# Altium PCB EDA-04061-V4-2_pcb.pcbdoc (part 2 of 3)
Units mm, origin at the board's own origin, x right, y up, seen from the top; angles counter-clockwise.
Board outline 105 x 56 mm, 6 copper layers (Top Layer, L2, L3, L4, L5, Bottom Layer), stack 1.58 mm thick; 213 components, 137 nets, 766 pads, 477 vias.
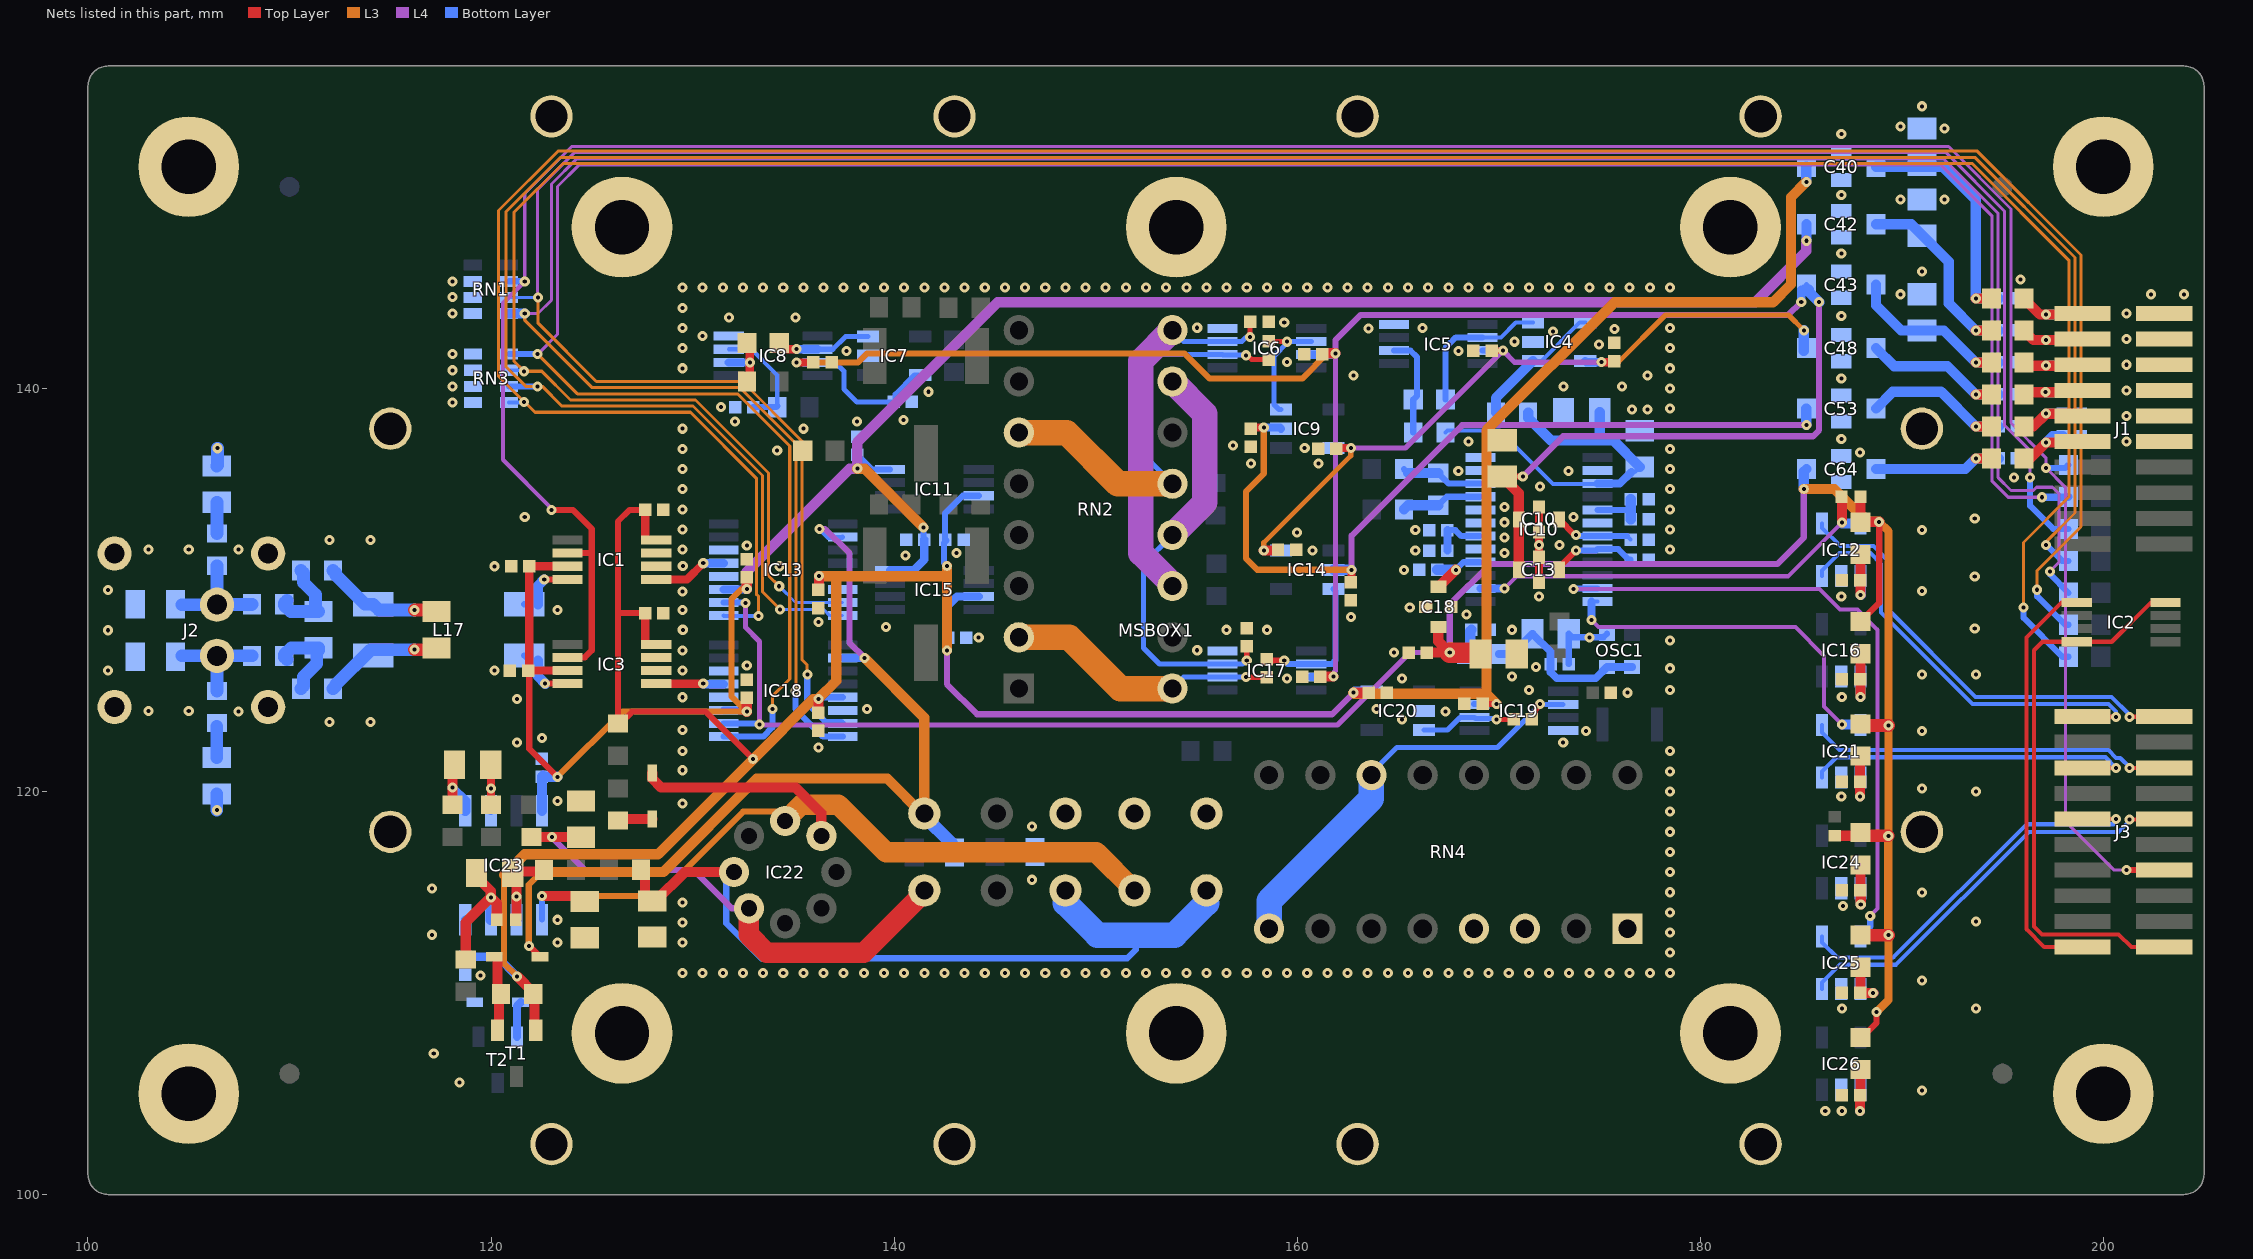
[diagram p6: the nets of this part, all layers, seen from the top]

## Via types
v1: diameter 0.5, hole 0.2, Top Layer to Bottom Layer, tented both sides, 477 vias

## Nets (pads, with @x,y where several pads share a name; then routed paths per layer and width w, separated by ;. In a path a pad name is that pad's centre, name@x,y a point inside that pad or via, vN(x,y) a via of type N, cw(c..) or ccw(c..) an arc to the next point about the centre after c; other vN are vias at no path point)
2V5_DIGITAL: C18.3 C21.2 C22.1 C64.1 C78.1 IC13.2 IC18.2 L7.1 L8.1 L9.1 L10.1 L11.2 L12.2 L20.1 R4.2 R18.2 | length 120
  Top Layer w0.305: L12.2@187.96,107.798 188.031,107.798 188.754,108.52 v1(188.754,109.061) ; L8.1@187.96,128.435 188.882,129.357 v1(188.882,133.381)
  Top Layer w0.508: C22.1@166.432,126.892 v1(167.572,126.892) 167.005,127.46 C18.3@167.005,128.159 ; C21.2@168.75,126.892 169.03,126.892 C21.2@169.1,126.822 ; R18.2@186.665,117.8 187.802,117.8 L10.1@187.96,117.958 ; R4.2@187.954,134.62 187.96,134.614 L7.1@187.96,133.356 187.985,133.381 v1(188.882,133.381)
  Top Layer w0.635: L11.2@187.96,112.878 187.968,112.869 v1(189.34,112.869) ; L10.1@187.96,117.958 188.118,117.8 v1(189.332,117.8) ; L9.1@187.96,123.355 188.038,123.277 v1(189.348,123.277)
  Top Layer w1.016: v1(167.572,126.892) C21.2@168.75,126.892
  L4 w0.254: v1(132.627,129.357) 132.627,128.147 133.325,127.449 v1(133.325,123.325) 133.35,123.3 162.002,123.3 165.594,126.892 v1(167.572,126.892)
  L4 w0.305: v1(167.572,126.892) 167.572,129.28 169.573,131.281 183.826,131.281 185.141,132.596 v1(185.141,135.009)
  L3 w0.406: v1(188.754,109.061) 189.34,109.647 v1(189.34,112.869) 189.332,112.877 v1(189.332,117.8) 189.348,117.816 v1(189.348,123.277) 189.348,132.915 v1(188.882,133.381)
  L3 w0.508: v1(185.141,135.009) 186.66,135.009 188.288,133.381 v1(188.882,133.381)
  Bottom Layer w0.305: IC13.2@131.547,129.376 132.608,129.376 v1(132.627,129.357) ; IC18.2@131.55,123.375 133.275,123.375 v1(133.325,123.325)
  Bottom Layer w0.508: L20.1@168.4,126.822 168.594,127.016 168.594,127.968 C78.1@168.65,128.024 ; v1(185.141,135.009) 185.141,135.866 C64.1@185.275,136
  Bottom Layer w0.635: v1(167.572,126.892) 168.33,126.892 L20.1@168.4,126.822
7V1: D2.1 IC13.10 IC18.10 R9.2 R12.2 R13.2 R38.2 RN4.1 RN4.3 RN4.4 | length 47.9
  Top Layer w0.305: v1(121.873,112.325) 121.912,112.325 D2.1@122.438,111.799
  L4 w0.305: v1(136.297,133.033) 136.571,133.033 137.795,131.809 137.795,127.364 v1(138.532,126.627)
  L3 w0.305: v1(121.873,112.325) 121.873,115.369 122.504,116
  L3 w0.508: 122.504,116 128.54,116 133.182,120.642 139.656,120.642 141.5,118.798 141.5,123.659 v1(138.532,126.627)
  Bottom Layer w0.254: v1(136.297,133.033) 136.734,132.596 137.417,132.596 IC13.10@137.447,132.626
  Bottom Layer w0.406: IC18.10@137.45,126.625 138.53,126.625 v1(138.532,126.627)
  Bottom Layer w0.635: R9.2@141.5,118.904 141.5,118.774 142.843,117.431 142.843,117.133 R38.2@143,116.975
+5V: C4.2 C5.1 C7.2 C10.1 C13.1 C24.2 C43.1 C56.2 IC6.7 IC7.5 IC8.7 IC17.7 | length 111.6
  Top Layer w0.305: C7.2@170.18,135.625 v1(171.196,135.625)
  Top Layer w0.406: v1(135.165,141.294) C5.1@136,141.294
  Top Layer w0.508: C24.2@161.15,125.7 v1(161.8,125.7) ; C4.2@161.25,141.7 161.29,141.74 v1(161.9,141.74) ; C7.2@170.18,135.625 171,134.805 C10.1@171,133.5 C13.1@171,131
  L4 w0.254: v1(161.8,125.7) 161.847,125.747 161.847,125.939 161.9,125.992 v1(161.9,141.74)
  L4 w0.305: v1(161.9,141.74) 161.9,142.4 163.145,143.645 184.379,143.645 v1(185.014,144.28) ; v1(171.196,135.625) 173.196,137.625 185.598,137.625 185.903,137.93 v1(185.903,144.28)
  L3 w0.305: v1(135.165,141.294) 138.213,141.294 138.659,141.74 154.404,141.74 155.652,140.492 160.252,140.492 161.5,141.74 v1(161.9,141.74)
  Bottom Layer w0.254: v1(135.165,141.294) 137.073,141.294 137.516,140.851 137.516,139.962 138.151,139.327 C56.2@139.987,139.327 140.056,139.327 140.056,139.708 141.017,140.669 IC7.5@141.3,140.669 ; v1@161.775,125.675 v1(161.8,125.7) ; v1@161.835,141.675 v1(161.9,141.74) ; C43.1@185.014,144.915 185.134,145.035 185.275,145.035 C43.1@185.275,145.15 185.453,144.973 C43.1@185.395,144.915
  Bottom Layer w0.406: IC17.7@160.7,125.675 v1@161.775,125.675 ; IC6.7@160.7,141.675 v1@161.835,141.675 ; v1(185.014,144.28) C43.1@185.014,144.915
  Bottom Layer w0.508: C43.1@185.395,144.915 185.395,144.788 v1(185.903,144.28)
+7.5V: C2.1 C3.2 C9.2 C12.1 C48.1 IC4.5 IC5.7 IC9.5 IC14.5 | length 40.3
  Top Layer w0.305: C3.2@169.65,141.879 v1(170.212,141.879)
  Top Layer w0.406: C9.2@161.95,137 161.991,137.041 v1(162.662,137.041) ; v1(175.108,141.301) 175.685,141.301 C2.1@175.743,141.359
  Top Layer w0.508: v1(158.344,131.961) 159.011,131.961 C12.1@159.05,132
  L4 w0.254: v1(162.662,137.041) 165.374,137.041 v1(170.212,141.879) 170.79,141.301 v1(175.108,141.301)
  L3 w0.254: v1(158.344,131.961) 158.344,132.342 162.662,136.66 v1(162.662,137.041) ; v1(175.108,141.301) 175.939,141.301 178.283,143.645 184.379,143.645 v1(185.141,142.883)
  Bottom Layer w0.203: C48.1@185.142,141.867 C48.1@185.275,142
  Bottom Layer w0.305: v1(158.344,131.961) 158.355,131.95 IC14.5@159.2,131.95 ; IC9.5@161.8,137.05 162.653,137.05 v1(162.662,137.041) ; IC5.7@169.2,141.879 v1(170.212,141.879)
  Bottom Layer w0.406: IC4.5@174.3,141.363 174.362,141.301 v1(175.108,141.301)
  Bottom Layer w0.508: C48.1@185.141,141.867 v1(185.141,142.883)
+15V: C11.2 C19.1 C20.2 C27.1 C28.2 C29.1 C40.1 C72.1 C79.2 C83.2 IC1.4 IC3.4 IC11.7 IC13.13 IC15.7 IC18.13 IC19.7 IC20.5 IC23.8 R8.2 R23.2 T1.1 | length 158.2
  Top Layer w0.305: IC3.4@127.65,127.3 IC3.4@128.2,127.3 ; C20.2@127.65,128.85 126.3,128.85 ; C11.2@127.65,133.975 126.876,133.975 126.3,133.399 126.3,128.85 ; v1(133.004,121.607) 130.65,123.96 127,123.96 126.415,123.375 R8.2@126.3,123.375 126.3,128.85 ; C28.2@169.2,124.341 v1(169.901,124.341)
  Top Layer w0.406: IC3.4@127.65,127.3 C20.2@127.65,128.85 ; C11.2@127.65,133.975 127.651,132.475 IC1.4@128.2,132.475
  Top Layer w0.508: v1(121.298,110.823) 122.098,110.023 R23.2@122.098,109.956 122.16,109.894 122.16,108.212 T1.1@122.221,108.15 ; C29.1@136.246,123.902 v1(136.246,124.595) ; C19.1@136.246,129.998 136.271,130.023 v1(136.271,130.683) ; v1(162.8,124.9) C27.1@163.55,124.9
  L4 w0.305: v1(142.621,127) 142.621,125.332 144.12,123.833 161.733,123.833 v1(162.8,124.9)
  L3 w0.305: 120.64,115.858 120.64,111.481 v1(121.298,110.823)
  L3 w0.508: 120.64,115.858 121.673,116.891 128.288,116.891 v1(133.004,121.607) 135.992,124.595 v1(136.246,124.595) 137.135,125.484 137.135,130.683 ; v1(136.271,130.683) 137.135,130.683 ; v1(142.621,127) 142.621,130.683 ; v1(142.621,131.191) 142.621,130.683 ; v1(162.8,124.9) 162.851,124.849 169.393,124.849 ; v1(169.901,124.341) 169.393,124.849 ; v1(185.268,150.249) 184.506,149.487 184.506,145.169 183.617,144.28 175.755,144.28 169.393,137.918 169.393,124.849 ; 137.135,130.683 142.621,130.683
  Bottom Layer w0.254: v1(142.621,127) v1@142.679,127.058 ; v1(162.8,124.9) v1@162.85,124.95 ; IC19.7@168.784,124.341 IC19.7@168.8,124.325
  Bottom Layer w0.305: v1(136.246,124.595) 136.326,124.675 IC18.13@137.45,124.675 ; C72.1@142.55,132.5 142.596,132.454 C72.1@142.53,132.388 ; v1(142.621,131.191) 142.469,131.343 142.469,132.327 C72.1@142.53,132.388 ; IC11.7@144.2,134.675 143.405,134.675 142.53,133.8 C72.1@142.53,132.388 ; IC19.7@168.784,124.341 v1(169.901,124.341)
  Bottom Layer w0.406: IC23.8@118.72,113.64 C83.2@118.72,111.799 120.322,111.799 v1(121.298,110.823) ; v1(136.271,130.683) 136.278,130.676 IC13.13@137.447,130.676 ; v1@142.679,127.058 C79.2@142.679,127.635 142.679,129.227 143.127,129.675 IC15.7@144.2,129.675
  Bottom Layer w0.508: v1@162.85,124.95 IC20.5@163.7,124.95 ; v1(185.268,150.249) 185.268,151.011 185.275,151.004 C40.1@185.275,151
-2.5V: C6.1 C17.1 C53.1 IC9.2 IC14.2 | length 42.8
  Top Layer w0.406: C6.1@157.709,137.999 157.767,138.057 v1(158.344,138.057) ; C17.1@162.662,130.379 162.7,130.417 v1(162.7,131)
  L4 w0.305: v1(162.7,131) 162.7,132.7 168.184,138.184 v1(185.268,138.184)
  L3 w0.305: v1(158.344,138.057) 158.344,135.771 157.455,134.882 157.455,131.568 158.023,131 v1(162.7,131)
  Bottom Layer w0.406: v1(158.344,138.057) 159.143,138.057 IC9.2@159.2,138
  Bottom Layer w0.508: IC14.2@161.8,131 v1(162.7,131) ; v1(185.268,138.184) 185.268,138.993 C53.1@185.275,139
-15V: C14.1 C15.2 C23.2 C26.1 C42.1 C63.1 C73.2 C82.2 IC1.7 IC3.7 IC11.4 IC13.3 IC15.4 IC18.3 IC23.4 | length 111.4
  Top Layer w0.305: C23.2@121.835,126 121.895,125.94 121.895,122.122 v1(123.292,120.725)
  Top Layer w0.406: IC3.7@123.8,126 C23.2@121.835,126 121.895,126.06 C15.2@121.895,131.175 IC1.7@123.8,131.175
  Top Layer w0.508: v1(132.69,123.96) C26.1@132.69,124.653 ; v1(132.69,130.056) C14.1@132.69,130.622
  L4 w0.508: v1(132.69,130.056) 132.69,130.912 137.795,136.017 v1(138.176,136.017) 138.176,137.32 145.136,144.28 182.728,144.28 185.268,146.82 v1(185.268,147.328)
  L3 w0.305: v1(123.292,120.725) 126.527,123.96 v1(132.69,123.96) 131.928,124.722 131.928,129.548 132.436,130.056 v1(132.69,130.056)
  L3 w0.508: v1(138.176,136.017) 138.54,136.017 v1(141.453,133.104)
  Bottom Layer w0.305: v1@132.625,124.025 v1(132.69,123.96) ; C63.1@138.176,136.71 138.911,135.975 IC11.4@139.8,135.975 ; v1(141.453,133.104) 141.453,132.547 C73.2@141.5,132.5 ; v1(185.268,147.328) v1@185.275,147.335
  Bottom Layer w0.406: IC13.3@131.547,130.026 132.66,130.026 v1(132.69,130.056) ; IC18.3@131.55,124.025 v1@132.625,124.025 ; v1(138.176,136.017) C63.1@138.176,136.71 ; IC15.4@139.8,130.975 140.961,130.975 141.5,131.514 C73.2@141.5,132.5
  Bottom Layer w0.508: IC23.4@122.53,119.04 122.527,119.043 122.527,120.722 C82.2@122.523,120.725 122.579,120.781 122.635,120.725 v1(123.292,120.725) ; v1@185.275,147.335 C42.1@185.275,148.15
A0_N: IC13.1 L19.2 RN3.8 | length 134.4
  L3 w0.152: v1(133.282,128.707) 133.282,129.672 133.166,129.787 133.166,135.549 129.896,138.819 122.181,138.819 121.673,139.327 v1(121.641,139.327) 120.371,140.597 120.371,148.825 123.319,151.773 193.75,151.773 198.9,146.623 198.9,133.139 196.716,130.955 v1(196.716,130.01)
  Bottom Layer w0.203: RN3.8@120.9,139.3 121.614,139.3 v1(121.641,139.327) ; IC13.1@131.547,128.726 131.566,128.707 v1(133.282,128.707)
  Bottom Layer w0.305: v1(196.716,130.01) 196.716,129.676 198.122,128.27 L19.2@198.272,128.27
A0_P: IC18.1 L14.2 RN3.5 | length 131.4
  L4 w0.152: v1(122.316,141.7) 123.302,142.687 123.302,150.019 124.376,151.093 191.944,151.093 194.469,148.568 194.469,135.414 195.282,134.6 v1(196.954,134.6)
  L3 w0.152: v1(122.316,141.7) 124.282,139.733 132.231,139.733 134.824,137.14 134.824,125.586 133.96,124.722 v1(133.96,124.087)
  Bottom Layer w0.305: RN3.5@120.9,141.7 v1(122.316,141.7) ; IC18.1@131.55,122.725 133.506,122.725 133.96,123.179 v1(133.96,124.087)
  Bottom Layer w0.381: v1(196.954,134.6) 198.253,134.6 L14.2@198.272,134.62
A1_N: IC13.16 L16.2 RN3.7 | length 131.6
  L3 w0.152: v1(134.341,129.04) 133.469,129.912 133.469,135.677 130.022,139.124 123.51,139.124 122.534,140.1 v1(122.316,140.1) 121.719,140.1 120.752,141.067 120.752,148.775 123.445,151.468 193.624,151.468 198.598,146.495 198.598,133.818 197.167,132.388 v1(197.167,132.239)
  Bottom Layer w0.152: v1(134.341,129.04) 136.5,129.04 136.814,128.726 IC13.16@137.447,128.726
  Bottom Layer w0.305: RN3.7@120.9,140.1 v1(122.316,140.1) ; v1(197.167,132.239) 197.961,131.445 L16.2@198.272,131.445
A1_P: IC18.16 L18.2 RN1.8 | length 136.1
  L4 w0.152: v1(121.673,143.715) 122.334,143.715 123,144.381 123,150.145 124.251,151.395 192.073,151.395 194.786,148.682 194.786,135.572 195.421,134.938 196.532,134.938 196.691,135.096 197.485,135.096 197.802,134.779 197.802,131.369 v1(197.358,130.924)
  L3 w0.152: v1(121.673,143.715) 121.673,143.387 125.022,140.038 132.353,140.038 135.126,137.266 135.126,124.999 v1(135.103,124.976)
  Bottom Layer w0.305: v1(135.103,124.976) 135.103,124.087 136.465,122.725 IC18.16@137.45,122.725 ; v1(197.358,130.924) 197.358,130.772 L18.2@198.272,129.857
  Bottom Layer w0.508: RN1.8@120.89,143.715 v1(121.673,143.715)
A2_N: IC13.15 L21.2 RN3.6 | length 134.3
  L3 w0.152: v1(134.3,130.183) 133.771,130.712 133.771,135.806 130.149,139.429 123.942,139.429 122.519,140.851 v1(121.641,140.851) 121.133,141.359 121.133,148.725 123.571,151.163 193.498,151.163 198.295,146.366 198.295,134.609 196.044,132.358 v1(196.044,129.127)
  Bottom Layer w0.152: RN3.6@120.9,140.9 121.592,140.9 v1(121.641,140.851) ; v1(134.3,130.183) 135.107,129.376 IC13.15@137.447,129.376
  Bottom Layer w0.305: v1(196.044,129.127) 196.044,128.609 197.97,126.682 L21.2@198.272,126.682
A2_P: IC18.15 L15.2 RN1.7 | length 131.2
  L4 w0.152: v1(122.32,144.501) 122.316,144.506 122.316,149.888 124.125,151.698 192.201,151.698 195.104,148.795 195.104,138.172 196.374,136.902 v1(196.374,135.572)
  L3 w0.152: v1(122.32,144.501) 122.32,143.251 125.228,140.343 132.476,140.343 135.433,137.386 135.433,126.535 135.682,126.287 135.682,125.822 v1(135.696,125.808)
  Bottom Layer w0.152: RN1.7@120.89,144.515 120.904,144.501 v1(122.32,144.501)
  Bottom Layer w0.305: v1(135.696,125.808) 135.694,125.806 135.694,124.366 136.612,123.448 137.377,123.448 IC18.15@137.45,123.375 ; v1(196.374,135.572) 196.374,134.167 197.508,133.032 L15.2@198.272,133.032
AIN+: C66.2 IC10.21 R30.2 | length 4.1
  Bottom Layer w0.305: C66.2@167,134.2 167.425,134.625 IC10.21@169.1,134.625
  Bottom Layer w0.508: R30.2@165.3,134 165.5,134.2 C66.2@167,134.2
AIN-: C66.1 IC10.22 R28.2 | length 4.1
  Bottom Layer w0.305: R28.2@165.3,136 R28.2@165.5,135.8 ; C66.1@167,135.8 167.525,135.275 IC10.22@169.1,135.275
  Bottom Layer w0.508: R28.2@165.5,135.8 C66.1@167,135.8
CS: IC10.14 IC12.5 R4.1 | length 21.5
  Top Layer w0.508: R4.1@187.014,134.62 187.034,134.6 v1(187.034,133.355)
  L4 w0.203: v1(170.282,130.075) 170.885,130.678 184.357,130.678 v1(187.034,133.355)
  Bottom Layer w0.406: IC10.14@169.1,130.075 v1(170.282,130.075)
  Bottom Layer w0.508: v1(187.034,133.355) 187.034,133.3 IC12.5@187.95,133.3
CS_DIFF_N: IC12.4 J3.2 | length 22.6
  Top Layer w0.203: v1(201.295,123.706) 203.02,123.706 J3.2@203.029,123.715
  Bottom Layer w0.203: IC12.4@186.05,133.3 186.05,133.084 186.956,132.178 188.59,132.178 189.332,131.436 189.332,129.033 193.669,124.697 200.406,124.697 201.295,123.808 v1(201.295,123.706)
CS_DIFF_P: IC12.3 J3.1 | length 21.8
  Top Layer w0.203: J3.1@198.965,123.715 198.974,123.706 v1(200.635,123.706)
  Bottom Layer w0.203: IC12.3@186.05,130.7 186.05,130.959 186.913,131.822 188.443,131.822 188.976,131.289 188.976,128.886 193.522,124.341 200.254,124.341 200.635,123.96 v1(200.635,123.706)
DIN: IC10.12 IC21.5 | length 18.2
  L4 w0.203: v1(174.604,128.502) 174.947,128.159 184.725,128.159 186.152,126.732 186.152,124.208 v1(187.035,123.325)
  Bottom Layer w0.203: IC10.12@174.604,129.417 174.6,129.421 174.604,129.425 IC10.12@174.9,129.425
  Bottom Layer w0.406: v1(174.604,128.502) IC10.12@174.604,129.417
  Bottom Layer w0.508: v1(187.035,123.325) 187.925,123.325 IC21.5@187.95,123.3
DIN_DIFF_N: IC21.4 J3.6 | length 18.2
  Top Layer w0.203: v1(201.295,121.158) 203.012,121.158 J3.6@203.029,121.175
  Bottom Layer w0.203: IC21.4@186.05,123.3 186.05,122.924 186.919,122.055 200.249,122.055 200.636,121.668 200.843,121.668 201.324,121.187 v1(201.295,121.158)
DIN_DIFF_P: IC21.3 J3.5 | length 17.1
  Top Layer w0.203: J3.5@198.965,121.175 198.974,121.166 v1(200.635,121.166)
  Bottom Layer w0.203: IC21.3@186.05,120.7 186.05,120.982 186.768,121.699 200.102,121.699 v1(200.635,121.166)
DOUT: IC10.11 IC25.5 | length 32.8
  L4 w0.203: v1(173.711,130.056) 185.91,130.056 186.934,129.032 187.796,129.032 188.805,128.023 188.805,114.193 v1(188.436,113.824)
  Bottom Layer w0.305: v1(173.711,130.056) 173.73,130.075 IC10.11@174.9,130.075 ; IC25.5@187.95,112.8 187.941,112.81 187.935,112.815 IC25.5@187.946,112.815 ; v1(188.436,113.824) 188.436,113.305 IC25.5@187.946,112.815 ; IC25.5@187.946,112.815 187.966,112.815 187.935,112.784 187.925,112.794 IC25.5@187.946,112.815
DOUT_DIFF_N: IC25.3 J3.10 | length 20.7
  Top Layer w0.203: v1(201.295,118.618) 203.012,118.618 J3.10@203.029,118.635
  Bottom Layer w0.203: IC25.3@186.05,110.2 186.05,110.518 186.936,111.404 189.725,111.404 196.312,117.991 200.762,117.991 201.295,118.524 v1(201.295,118.618)
DOUT_DIFF_P: IC25.4 J3.9 | length 19.8
  Top Layer w0.203: J3.9@198.965,118.635 200.626,118.635 v1(200.635,118.626)
  Bottom Layer w0.203: IC25.4@186.05,112.8 186.05,112.51 186.8,111.76 189.578,111.76 196.19,118.372 200.508,118.372 200.635,118.499 v1(200.635,118.626)
GND: B1.1 B2.1 B3.1 B4.1 B5.1 B6.1 B7.1 B8.1 B9.1 B10.1 C2.2 C3.1 C4.1 C5.2 C6.2 C7.1 C8.1 C9.1 C10.2 C11.1 C12.2 C13.2 C14.2 C15.1 C16.2 C17.2 C18.2 C19.2 C20.1 C21.1 C22.2 C23.1 C24.1 C25.2 C26.2 C27.2 C28.1 C29.2 C31.2 C32.1 C34.2 C35.1 C36.1 C37.2 C38.2 C39.2 C40.2 C41.2 C42.2 C43.2 C44.2 C45.2 C46.1 C47.2 C48.2 C49.1 C50.2 C51.1 C52.1 C53.2 C55.2 C56.1 C57.1 C58.1 C59.1 C60.1 C61.2 C62.1 C63.2 C64.2 C65.2 C67.1 C68.1 C69.2 C70.1 C71.1 C72.2 C73.1 C74.2 C75.1 C76.1 C77.1 C78.2 C79.1 C80.2 C81.1 C82.1 C83.1 C85.1 C89.1 C91.1 D3.1 IC1.2 IC1.3 IC3.2 IC3.3 IC4.2 IC5.4 IC6.4 IC7.2 IC8.4 IC10.2 IC10.6 IC10.17 IC10.19 IC10.20 IC10.23 IC10.24 IC12.2 IC13.4 IC13.6 IC13.14 IC16.2 IC17.4 IC18.4 IC18.6 IC18.14 IC19.4 IC20.2 IC21.2 IC24.2 IC25.2 IC26.2 J1.2 J1.4 J1.6 J1.8 J1.10 J1.12 J2.3 MSBOX1.1 MSBOX1.2 MSBOX1.3 MSBOX1.4 MSBOX1.5 MSBOX1.6 MSBOX1.7 MSBOX1.8 MSBOX1.9 MSBOX1.10 MSBOX1.11 MSBOX1.12 OSC1.2 R11.1 R31.1 R34.1 R37.1 RN1.1 RN1.2 RN1.3 RN3.1 RN3.2 RN3.3 RN3.4 | length 9
  Top Layer w0.406: C13.2@172,130.375 C13.2@172,131.625 C10.2@172,132.875 C10.2@172,134.125
  Bottom Layer w0.305: C80.2@173.475,126.325 C77.1@173.475,127.825 173.65,127.65 v1(174.5,127.65) 175.2,127.65 OSC1.2@175.375,127.825
  Bottom Layer w0.635: v1(106.394,119.07) C81.1@106.394,119.881 ; C70.1@106.394,136.155 106.425,136.186 v1(106.425,137.033)
  other v1: 186.205,104.148 187.025,104.148 191,105.164 118.427,105.569 117.157,106.998 187.035,109.228 193.675,109.228 191,110.62 119.471,110.861 129.5,111 130.5,111 131.5,111 132.5,111 133.5,111 134.5,111 135.5,111 136.5,111 137.5,111 138.5,111 139.5,111 140.5,111 141.5,111 142.5,111 143.5,111 144.5,111 145.5,111 146.5,111 147.5,111 148.5,111 149.5,111 150.5,111 151.5,111 152.5,111 153.5,111 154.5,111 155.5,111 156.5,111 157.5,111 158.5,111 159.5,111 160.5,111 161.5,111 162.5,111 163.5,111 164.5,111 165.5,111 166.5,111 167.5,111 168.5,111 169.5,111 170.5,111 171.5,111 172.5,111 173.5,111 174.5,111 175.5,111 176.5,111 177.5,111 178.5,111 178.5,112 123.292,112.5 129.5,112.5 117.069,112.889 178.5,113 129.5,113.5 193.675,113.538 123.292,113.634 178.5,114 187.076,114.308 129.5,114.5 191,114.984 178.5,115 117.069,115.192 146.844,115.619 178.5,116 178.5,117 178.5,118 146.844,118.269 178.5,119 129.5,119.41 123.292,119.526 187,119.757 178.5,120 193.675,119.998 191,120.15 178.5,121 129.5,121.053 129.5,122 178.5,122 136.246,122.182 121.298,122.436 173.203,122.436 122.53,122.65 174.331,122.998 191,122.998 129.5,123.05 111.989,123.452 114.021,123.452 165.202,123.579 107.474,123.96 167.361,123.96 103,124 105,124 138.659,124.087 163.932,124.087 121.298,124.595 129.5,124.675 187.025,124.697 176.39,124.9 171.5,125.025 178.5,125.025 159.487,125.611 165.202,125.611 170.663,125.7 191,125.802 193.675,125.802 101,126 120.177,126 129.5,126 178.5,126.114 171.848,126.175 132.69,126.246 164.8,126.892 129.5,127 155.042,127.008 178.5,127.5 144.2,127.635 101,128 129.515,128.024 156.5,128.024 158.494,128.024 170.663,128.024 193.624,128.08 139.605,128.159 136.246,128.405 162.662,128.659 168.4,128.788 123.292,129 129.5,129 165.588,129.139 172.009,129.675 187,129.675 129.5,129.921 191,129.945 101,130 193.624,130.675 165.3,131 120.177,131.175 134.317,131.175 129.515,131.191 140.564,131.707 143.104,131.834 170.282,131.834 160.757,131.961 165.862,131.953 103,132 105,132 107.474,132 129.5,132 178.5,132 132.69,132.215 172.009,132.24 173.025,132.24 111.989,132.469 114.021,132.469 170.282,132.596 159.995,132.85 165.862,132.969 191,132.969 129.5,133 178.5,133 170.282,133.358 193.624,133.555 121.673,133.612 173.711,133.612 129.5,134 178.5,134 170.282,134.12 129.5,135 178.5,135 172.06,135.136 195.58,135.572 167.996,135.898 173.457,135.898 129.5,136 178.5,136 157.709,136.279 161.05,136.279 187.925,136.816 134.201,136.912 129.5,137 178.5,137 160.376,137.041 156.82,137.168 168.5,137.365 201.143,137.365 187,137.5 129.5,138 135.5,138 132.113,138.35 138.151,138.35 140.462,138.43 201.143,138.635 176.625,138.946 177.394,138.946 178.5,139 131.42,139.073 118.087,139.3 141.705,139.835 201.143,139.905 178.5,140 118.087,140.1 173.215,140.1 176.124,140.1 187,140.5 162.8,140.644 177.394,140.644 118.087,140.9 129.5,141 178.5,141 201.143,141.175 159.487,141.301 118.087,141.7 137.643,141.867 168,141.867 129.5,142 178.5,142 174.981,142.19 170.79,142.317 201.143,142.445 130.5,142.594 172.695,142.825 175.743,142.952 163.55,142.975 129.5,143 155.042,143.01 166.23,143 178.5,143 159.36,143.266 131.8,143.518 135.103,143.518 187,143.6 118.087,143.715 201.143,143.715 129.5,144 118.087,144.534 189.942,144.672 202.372,144.672 204,144.672 129.5,145 130.5,145 131.5,145 132.5,145 133.5,145 134.5,145 135.5,145 136.5,145 137.5,145 138.5,145 139.5,145 140.5,145 141.5,145 142.5,145 143.5,145 144.5,145 145.5,145 146.5,145 147.5,145 148.5,145 149.5,145 150.5,145 151.5,145 152.5,145 153.5,145 154.5,145 155.5,145 156.5,145 157.5,145 158.5,145 159.5,145 160.5,145 161.5,145 162.5,145 163.5,145 164.5,145 165.5,145 166.5,145 167.5,145 168.5,145 169.5,145 170.5,145 171.5,145 172.5,145 173.5,145 174.5,145 175.5,145 176.5,145 177.5,145 178.5,145 118.087,145.315 195.897,145.415 191,145.8 187,146.7 189.942,149.373 192.126,149.373 187,149.6 187,152.631 192.126,152.9 189.942,153 191,154
IN+: J2.1 R31.2 R32.1 R41.1 | length 5.4
  L4 w0.635: J2.1@106.401,129.27 J2.1@106.425,129.27
  Bottom Layer w0.635: R31.2@104.656,129.27 J2.1@106.401,129.27 ; R32.1@106.401,131.2 J2.1@106.401,129.27 ; R41.1@108.141,129.294 108.129,129.282 106.413,129.282 J2.1@106.401,129.27
IN-: J2.2 R34.2 R35.1 R39.1 | length 5.2
  L4 w0.635: J2.2@106.401,126.73 J2.2@106.401,126.754
  Bottom Layer w0.635: R34.2@104.656,126.73 J2.2@106.401,126.73 R39.1@108.141,126.73 ; R35.1@106.401,124.99 J2.2@106.401,126.69
IN_CPL: IC1.6 IC3.6 J3.14 L13.2 RN1.6 | length 143.5
  Top Layer w0.305: v1(123,133.975) 124.058,133.975 125,133.033 125,131.825 ; IC3.6@123.8,126.65 124.65,126.65 125,127 125,131.825 ; IC1.6@123.8,131.825 125,131.825 ; v1(201.143,116.095) J3.14@203.029,116.095
  L4 w0.152: v1(121.673,145.315) 121.673,149.673 124,152 192.327,152 195.421,148.905 195.421,138.282 197.167,136.536 v1(197.167,136.049) 198.12,135.096 198.12,118.522 200.547,116.095 v1(201.143,116.095)
  L4 w0.203: v1(121.673,145.315) 120.585,144.227 120.585,136.461 123,134.046 v1(123,133.975)
  Bottom Layer w0.305: RN1.6@120.89,145.315 v1(121.673,145.315) ; v1(197.167,136.049) 198.114,136.049 L13.2@198.272,136.207
NetC1_1: C1.1 IC7.3 IC8.6 | length 4.8
  Top Layer w0.406: C1.1@134.3,142.259 134.611,141.948 v1(135.165,141.948)
  Bottom Layer w0.254: IC8.6@136.2,141.944 136.958,141.944 137.583,142.569 IC7.3@138.7,142.569
  Bottom Layer w0.406: v1(135.165,141.948) 136.196,141.948 IC8.6@136.2,141.944
NetC1_2: C1.2 IC8.2 R3.1 | length 3.1
  Top Layer w0.406: R3.1@132.7,140.35 132.842,140.492 v1(132.842,141.294) 132.842,142.117 C1.2@132.7,142.259
  Bottom Layer w0.406: IC8.2@131.8,141.294 v1(132.842,141.294)
NetC10_3: C10.3 C71.2 IC10.7 | length 4
  Top Layer w0.305: C10.3@173,133.5 173.777,132.723 v1(173.838,132.723)
  Bottom Layer w0.203: v1(173.838,132.723) 173.873,132.723 v1@173.921,132.675 ; C71.2@176.375,132.675 C71.2@176.55,132.5
  Bottom Layer w0.305: v1@173.921,132.675 IC10.7@174.9,132.675 C71.2@176.375,132.675
NetC13_3: C13.3 C75.2 IC10.8 | length 4.3
  Top Layer w0.305: C13.3@173,131 173,131.123 v1(173.838,131.961)
  Bottom Layer w0.203: IC10.8@174.875,132 IC10.8@174.9,132.025
  Bottom Layer w0.305: v1(173.838,131.961) 174.836,131.961 IC10.8@174.875,132 ; IC10.8@174.9,132.025 175.933,132.025 176.458,131.5 C75.2@176.55,131.5
NetC16_1: C16.1 IC12.1 L7.2 | length 3
  Top Layer w0.508: v1(187.959,129.75) 187.959,130.467 C16.1@187.934,130.493 187.96,130.519 L7.2@187.96,131.756
  Bottom Layer w0.508: IC12.1@187.95,130.7 187.976,130.675 187.976,129.767 v1(187.959,129.75)
NetC18_1: C18.1 C76.2 IC10.16 | length 3.5
  Top Layer w0.508: C18.1@167.005,130.159 167.034,130.159 v1(167.875,131)
  Bottom Layer w0.305: v1(167.875,131) 168.25,131.375 IC10.16@169.1,131.375
  Bottom Layer w0.508: C76.2@166.95,131 v1(167.875,131)
NetC25_1: C25.1 IC16.1 L8.2 | length 3.2
  Top Layer w0.508: v1(187.951,124.697) 187.951,125.554 C25.1@187.934,125.571 187.96,125.598 L8.2@187.96,126.835
  Bottom Layer w0.508: v1(187.951,124.697) IC16.1@187.95,125.7
NetC30_1: C30.1 IC23.2 R16.2 | length 3.1
  Top Layer w0.406: C30.1@119.989,121.331 119.999,121.321 v1(119.999,120.146) ; R16.2@120,119.34 v1@119.999,120.146
  Bottom Layer w0.406: IC23.2@119.99,119.04 119.999,119.049 v1(119.999,120.146)
NetC30_2: C30.2 IC23.1 R15.1 | length 3.4
  Top Layer w0.508: R15.1@118.087,119.34 v1(118.087,120.188) 118.087,121.229 C30.2@118.189,121.331
  Bottom Layer w0.508: v1(118.087,120.188) 118.087,120.148 118.72,119.515 IC23.1@118.72,119.04
NetC31_1: C31.1 IC21.1 L9.2 | length 3
  Top Layer w0.508: v1(187.931,119.757) 187.934,119.76 C31.1@187.934,120.491 187.934,121.729 L9.2@187.96,121.755
  Bottom Layer w0.508: v1(187.931,119.757) 187.931,120.681 IC21.1@187.95,120.7
NetC32_2: C32.2 IC22.5 R9.1 R17.1 | length 25.4
  Top Layer w0.508: R17.1@122,117.74 v1(123.024,117.74) 124.453,117.74 C32.2@124.467,117.726
  Top Layer w1.016: IC22.5@132.799,114.204 132.799,112.878 133.677,112 138.5,112 141.5,115 R9.1@141.5,115.094
  L4 w0.305: v1(123.024,117.74) 124.669,116.095 130.051,116.095 131.942,114.204 IC22.5@132.799,114.204
NetC33_1: C33.1 IC23.7 R21.1 R22.2 | length 7.4
  Top Layer w0.508: R22.2@118.745,111.661 118.745,113.504 v1(119.99,114.749) ; C33.1@119.277,115.951 119.277,115.776 119.99,115.063 v1(119.99,114.749) ; R21.1@120.282,113.634 120.282,114.457 v1(119.99,114.749)
  Bottom Layer w0.508: IC23.7@119.99,113.64 v1(119.99,114.749)
NetC33_2: C33.2 IC23.6 R20.2 R21.2 | length 5.2
  Top Layer w0.508: R21.2@121.222,113.634 121.26,113.672 v1(121.26,114.787) 121.26,115.768 C33.2@121.077,115.951 121.156,116.03 122.545,116.03 R20.2@122.624,116.109
  Bottom Layer w0.508: IC23.6@121.26,113.64 v1(121.26,114.787)
NetC34_1: C34.1 IC24.1 L10.2 | length 2.8
  Top Layer w0.508: L10.2@187.96,116.357 187.96,115.12 C34.1@187.934,115.094 187.966,115.061 v1(187.966,114.391)
  Bottom Layer w0.508: IC24.1@187.95,115.2 187.966,115.184 v1(187.966,114.391)
NetC35_2: C35.2 IC22.6 R11.2 R13.1 R19.1 | length 39.4
  Top Layer w0.508: R19.1@127.445,116.115 127.641,115.919 127.641,114.843 127.912,114.572 C35.2@128,114.572 128.175,114.572 129.603,116 IC22.6@132.055,116
  Bottom Layer w0.305: IC22.6@132.055,116 131.674,115.619 131.674,113.464 133.411,111.727 151.572,111.727 151.994,112.149 151.994,112.873
  Bottom Layer w1.27: R11.2@148.5,114.46 150.087,112.873 151.994,112.873 153.913,112.873 R13.1@155.5,114.46
NetC36_2: C36.2 IC22.8 IC23.5 R12.1 | length 36.8
  Top Layer w0.508: v1(122.53,114.808) 124.382,114.808 C36.2@124.65,114.54
  L3 w0.254: IC22.8@134.595,118.54 IC22.8@135.095,119.04
  L3 w0.305: v1(122.53,114.808) 128.323,114.808 132.515,119 134.135,119 IC22.8@134.595,118.54
  L3 w1.016: IC22.8@135.095,119.04 135.395,119.34 137.24,119.34 139.605,116.975 150.042,116.975 R12.1@151.924,115.094
  Bottom Layer w0.305: IC23.5@122.53,113.64 v1(122.53,114.808)
NetC37_1: C37.1 IC25.1 L11.1 | length 2.7
  Top Layer w0.508: L11.1@187.96,111.277 187.96,110.04 C37.1@187.934,110.014 187.947,110 v1(188.582,110)
  Bottom Layer w0.508: IC25.1@187.95,110.2 187.95,110.046 187.996,110 v1(188.582,110)
NetC38_1: C38.1 IC26.1 L12.1 | length 3.1
  Top Layer w0.508: v1(187.931,104.148) 187.934,104.151 C38.1@187.934,104.934 187.96,104.96 L12.1@187.96,106.197
  Bottom Layer w0.508: v1(187.931,104.148) 187.931,105.181 IC26.1@187.95,105.2
NetC39_1: C39.1 C40.3 C45.1 L1.2 | length 12.5
  Top Layer w0.508: v1(193.675,144.463) L1.2@194.462,144.463
  Bottom Layer w0.508: C40.3@188.725,151 192.037,151 193.675,149.362 v1(193.675,144.463) C45.1@194.813,144.463
NetC41_1: C41.1 C42.3 C47.1 L2.2 | length 10.3
  Top Layer w0.508: v1(193.675,142.875) L2.2@194.462,142.875
  Bottom Layer w0.508: C42.3@188.725,148.15 190.468,148.15 191.046,147.572 192.328,146.29 192.328,144.222 v1(193.675,142.875) C47.1@194.813,142.875
NetC43_3: C43.3 C44.1 C50.1 L3.2 | length 9.1
  Top Layer w0.508: v1(193.675,141.287) L3.2@194.462,141.287
  Bottom Layer w0.508: C43.3@188.725,145.15 188.725,144.125 189.978,142.872 C44.1@191,142.872 192.09,142.872 v1(193.675,141.287) C50.1@194.813,141.287
NetC46_2: C46.2 J1.1 L1.1 | length 4.1
  Top Layer w0.508: L1.1@196.063,144.463 196.856,143.669 v1(197.167,143.669) 198.919,143.669 J1.1@198.965,143.715
  Bottom Layer w0.508: v1(197.167,143.669) 197.954,143.669 C46.2@198,143.715
NetC48_3: C48.3 C55.1 L4.2 | length 7.8
  Top Layer w0.508: v1(193.675,139.7) L4.2@194.462,139.7
  Bottom Layer w0.508: C48.3@188.725,142 189.62,141.105 192.27,141.105 v1(193.675,139.7) C55.1@194.813,139.7
NetC49_2: C49.2 J1.3 L2.1 | length 4
  Top Layer w0.508: L2.1@196.063,142.875 196.539,142.399 v1(197.167,142.399) 198.919,142.399 J1.3@198.965,142.445
  Bottom Layer w0.508: v1(197.167,142.399) 197.954,142.399 C49.2@198,142.445
NetC51_2: C51.2 J1.5 L3.1 | length 3.9
  Top Layer w0.508: L3.1@196.063,141.287 196.221,141.129 v1(197.167,141.129) 198.919,141.129 J1.5@198.965,141.175
  Bottom Layer w0.508: v1(197.167,141.129) 197.98,141.129 C51.2@198.026,141.175
NetC52_2: C52.2 J1.7 L4.1 | length 3.9
  Top Layer w0.508: L4.1@196.063,139.7 196.175,139.812 v1(197.129,139.812) 198.872,139.812 J1.7@198.965,139.905
  Bottom Layer w0.508: v1(197.129,139.812) 197.941,139.812 C52.2@197.988,139.859
NetC53_3: C53.3 C61.1 L5.2 | length 7.9
  Top Layer w0.508: v1(193.675,138.112) L5.2@194.462,138.112
  Bottom Layer w0.508: C53.3@188.725,139 189.56,139.835 191.952,139.835 v1(193.675,138.112) C61.1@194.813,138.112
NetC54_1: C54.1 IC4.3 IC5.6 | length 7.4
  Bottom Layer w0.203: IC5.6@169.2,142.529 170.113,142.529 170.847,143.263 IC4.3@171.7,143.263
  Bottom Layer w0.305: C54.1@167.361,139.45 167.361,142.009 167.881,142.529 IC5.6@169.2,142.529
NetC54_2: C54.2 IC5.2 R27.1 | length 5.1
  Bottom Layer w0.305: IC5.2@164.8,141.879 165.625,141.879 165.949,141.555 165.949,139.638 C54.2@165.761,139.45 R27.1@165.761,137.81
NetC57_2: C57.2 C60.2 IC10.3 R26.2 R27.2 | length 19.3
  Bottom Layer w0.203: R27.2@167.361,137.81 167.459,137.908 170.05,137.908 172.695,135.263 174.888,135.263 IC10.3@174.9,135.275 ; C60.2@176.588,135.854 176.754,135.854 C60.2@177,136.1
  Bottom Layer w0.406: IC10.3@174.9,135.275 176.009,135.275 C60.2@176.588,135.854
  Bottom Layer w0.508: R26.2@171.463,138.808 171.463,138.534 172.575,137.422 175,137.422 ; C57.2@175.015,138.819 175.015,137.437 175,137.422 ; C60.2@177,136.1 175.678,137.422 175,137.422
NetC58_2: C58.2 IC8.3 R25.2 | length 5.7
  Bottom Layer w0.203: IC8.3@131.8,141.944 132.919,141.944 134.2,140.663 R25.2@134.2,139.119
  Bottom Layer w0.305: C58.2@133.013,139.073 134.154,139.073 R25.2@134.2,139.119
NetC59_2: C59.2 J1.9 L5.1 | length 4
  Top Layer w0.508: L5.1@196.063,138.112 196.532,138.112 v1(197.167,138.748) 198.853,138.748 J1.9@198.965,138.635
  Bottom Layer w0.508: v1(197.167,138.748) C59.2@197.988,138.748
NetC62_2: C62.2 J1.11 L6.1 | length 4.2
  Top Layer w0.508: L6.1@196.063,136.525 196.374,136.525 v1(197.167,137.319) 198.919,137.319 J1.11@198.965,137.365
  Bottom Layer w0.508: v1(197.167,137.319) 197.485,137.636 C62.2@197.988,137.636
NetC64_3: C64.3 C65.1 L6.2 | length 7.1
  Top Layer w0.508: v1(193.675,136.525) L6.2@194.462,136.525
  Bottom Layer w0.508: C64.3@188.725,136 193.15,136 v1(193.675,136.525) C65.1@194.813,136.525
NetC67_2: C67.2 C68.2 IC10.5 | length 2.7
  Bottom Layer w0.305: IC10.5@174.9,133.975 176.525,133.975 176.55,134
  Bottom Layer w0.508: C68.2@176.55,133.5 176.55,134 C67.2@176.55,134.5
NetC69_1: C69.1 C74.1 IC10.18 | length 2.8
  Bottom Layer w0.305: C69.1@167.455,132.969 167.854,132.969 168.148,132.675 IC10.18@169.1,132.675
  Bottom Layer w0.406: C74.1@167.455,131.953 C69.1@167.455,132.969
NetC70_2: C70.2 R32.2 | length 1.6
  Bottom Layer w0.635: C70.2@106.394,134.355 106.397,134.351 106.397,132.804 R32.2@106.401,132.8
NetC77_2: C77.2 C80.1 L20.2 OSC1.1 OSC1.4 | length 8.8
  Bottom Layer w0.381: L20.2@170,126.822 170.672,126.822 C77.2@171.675,127.825 172.575,126.925 C80.1@172.575,126.325 172.575,125.921 172.886,125.611 174.811,125.611 OSC1.1@175.375,126.175 OSC1.4@176.625,126.175
NetC81_2: C81.2 R35.2 | length 1.5
  Bottom Layer w0.635: C81.2@106.394,121.681 R35.2@106.394,123.231
NetC84_1: C84.1 IC17.2 RN2.2 RN2.16 | length 13.6
  Top Layer w0.254: v1(157.455,125.675) 157.461,125.669 158.494,125.669 C84.1@158.5,125.664
  L3 w1.27: RN2.2@146.19,127.65 148.685,127.65 151.235,125.1 153.8,125.1 RN2.16@153.81,125.11
  Bottom Layer w0.254: RN2.16@153.81,125.11 154.375,125.675 IC17.2@156.3,125.675 v1(157.455,125.675)
NetC84_2: C84.2 IC14.3 IC17.6 | length 7.2
  Top Layer w0.305: C84.2@158.5,126.564 158.564,126.5 v1(159.36,126.5)
  Bottom Layer w0.305: v1(159.36,126.5) 159.535,126.325 IC17.6@160.7,126.325 161.725,126.325 161.9,126.5 161.9,129.95 IC14.3@161.8,130.05
NetC85_2: C85.2 IC17.3 RN2.10 RN2.13 | length 21.4
  Top Layer w0.254: v1(157.5,126.5) C85.2@157.5,127.2
  L4 w1.27: RN2.13@153.81,132.73 155.423,134.343 155.423,138.737 RN2.10@153.81,140.35
  Bottom Layer w0.254: RN2.13@153.81,132.73 152.375,131.295 152.375,127.125 153.175,126.325 IC17.3@156.3,126.325 157.289,126.325 157.464,126.5 v1(157.5,126.5) v1@157.464,126.536
NetC86_1: C86.1 R41.2 R42.1 | length 4.5
  Bottom Layer w0.635: R41.2@109.873,129.477 109.741,129.344 R41.2@109.741,129.294 109.741,129.244 110.061,128.924 111.143,128.924 111.435,128.924 111.287,129.071 111.287,129.774 110.696,130.366 110.696,130.836 R42.1@110.563,130.969
NetC86_2: C86.2 R39.2 R40.1 | length 4.6
  Bottom Layer w0.635: R39.2@109.873,126.547 109.741,126.68 109.785,126.724 109.746,126.724 R39.2@109.741,126.73 109.741,126.78 110.085,127.124 111.435,127.124 C86.2@111.442,127.132 111.442,127.012 111.355,126.924 111.355,126.357 110.696,125.698 110.696,125.228 R40.1@110.563,125.095
NetC87_1: C87.1 L17.2 R42.2 | length 6
  Top Layer w0.635: v1(116.205,129) 117.188,129 117.2,129.011 C87.1@117.287,128.924
  Bottom Layer w0.635: R42.2@112.163,130.969 112.296,130.836 112.296,130.746 113.748,129.294 L17.2@114.148,129.294 114.442,129 v1(116.205,129)
NetC87_2: C87.2 L17.1 R40.2 | length 6
  Top Layer w0.635: v1(116.205,127.037) 117.2,127.037 C87.2@117.287,127.124
  Bottom Layer w0.635: R40.2@112.163,125.095 112.296,125.228 112.296,125.302 114.031,127.037 v1(116.205,127.037)
NetC88_1: C88.1 IC6.2 RN2.6 RN2.12 | length 21.5
  Top Layer w0.254: v1(157.47,141.645) 157.526,141.645 157.742,141.429 C88.1@158.582,141.429
  L3 w1.27: RN2.6@146.19,137.81 148.558,137.81 151.098,135.27 RN2.12@153.81,135.27
  Bottom Layer w0.254: RN2.12@153.81,135.27 152.375,136.705 152.375,140.875 153.175,141.675 IC6.2@156.3,141.675 156.315,141.66 157.455,141.66 v1(157.47,141.645)
NetC88_2: C88.2 IC6.6 IC9.3 | length 5.9
  Top Layer w0.254: C88.2@158.582,142.329 159.488,142.329 v1(159.5,142.317)
  Bottom Layer w0.254: 158.844,139.646 158.852,139.638 ; IC9.3@159.2,138.95 159.102,138.95 158.852,139.2 158.852,139.638 ; v1@159.528,142.289 158.852,141.613 158.852,139.638 ; v1@159.564,142.325 IC6.6@160.7,142.325
NetC89_2: C89.2 IC6.3 RN2.9 RN2.14 | length 18.7
  Top Layer w0.254: v1(157.651,142.56) 157.666,142.576 157.666,143.284 C89.2@157.682,143.3
  L4 w0.635: RN2.14@153.81,130.19 RN2.14@153.81,130.272
  L4 w1.27: RN2.14@153.81,130.272 152.248,131.834 152.248,141.359 153.779,142.89 RN2.9@153.81,142.89
  Bottom Layer w0.254: RN2.9@153.81,142.89 154.375,142.325 IC6.3@156.3,142.325 157.251,142.325 v1@157.455,142.529
NetC90_1: C90.1 IC19.2 RN4.8 RN4.11 | length 21.4
  Top Layer w0.254: C90.1@171.646,123.579 171.829,123.762 171.829,124.043 172.06,124.274 v1(172.06,124.341)
  Bottom Layer w0.254: RN4.11@163.678,120.81 RN4.11@163.69,120.81 163.69,120.924 164.948,122.182 169.943,122.182 v1@172.023,124.262 ; 172.325,124.325 IC19.2@173.2,124.325
  Bottom Layer w1.27: RN4.8@158.61,113.19 158.61,114.574 163.678,119.642 RN4.11@163.678,120.81
NetC90_2: C90.2 IC19.6 IC20.3 | length 4.7
  Top Layer w0.254: v1(169.901,123.579) C90.2@170.746,123.579
  Bottom Layer w0.254: IC20.3@166.3,123.05 167.455,123.05 168.08,123.675 IC19.6@168.8,123.675 168.849,123.626 169.854,123.626 v1(169.901,123.579)
NetD1_1: D1.1 IC22.1 | length 10.5
  Top Layer w0.508: D1.1@128,120.909 128,120.642 128.448,120.194 135.123,120.194 136.391,118.926 IC22.1@136.391,117.796
NetD1_2: D1.2 R14.1 | length 1.7
  Top Layer w0.508: R14.1@126.3,118.554 126.375,118.629 D1.2@128,118.629
NetD2_2: D2.2 R23.1 T1.2 | length 3.9
  Top Layer w0.254: D2.2@120.158,111.799 120.3,111.799 D2.2@120.324,111.775
  Top Layer w0.508: T1.2@120.321,108.15 120.392,108.221 120.392,109.85 R23.1@120.498,109.956 120.324,110.129 D2.2@120.324,111.775
NetD3_2: D3.2 T2.2 | length 1.8
  Bottom Layer w0.406: T2.2@121.283,107.83 121.283,109.348 D3.2@121.473,109.537
NetIC1_1: IC1.1 IC13.5 | length 3.7
  Top Layer w0.406: IC1.1@128.2,130.525 129.73,130.525 v1(130.531,131.326)
  Bottom Layer w0.406: v1(130.531,131.326) IC13.5@131.547,131.326
NetIC1_8: IC1.8 L17.3 | length 3.2
  Top Layer w0.305: v1(122.64,130.525) IC1.8@123.8,130.525
  Bottom Layer w0.305: L17.3@121.648,129.294 L17.3@122.334,129.294
  Bottom Layer w0.508: L17.3@122.334,129.294 122.334,130.219 v1(122.64,130.525)
NetIC2_1: IC2.1 J3.19 | length 20.8
  Top Layer w0.203: IC2.1@198.689,129.38 197.927,129.38 196.19,127.643 196.19,113.165 197.07,112.285 J3.19@198.965,112.285
NetIC2_4: IC2.4 IC2.8 J3.20 | length 28.1
  Top Layer w0.203: J3.20@203.029,112.285 201.406,112.285 201.397,112.276 200.764,112.909 196.954,112.909 196.571,113.292 196.571,127.008 196.993,127.43 IC2.4@198.689,127.43 200.422,127.43 202.372,129.38 IC2.8@203.089,129.38
NetIC3_1: IC3.1 IC18.5 | length 3.4
  Top Layer w0.406: IC3.1@128.2,125.35 130.524,125.35 v1(130.531,125.357)
  Bottom Layer w0.406: v1(130.531,125.357) 130.525,125.357 130.525,125.325 IC18.5@131.55,125.325
NetIC3_8: IC3.8 L17.4 | length 3.2
  Top Layer w0.305: v1(122.688,125.35) IC3.8@123.8,125.35
  Bottom Layer w0.305: L17.4@121.648,126.754 121.902,126.5 L17.4@122.334,126.5
  Bottom Layer w0.508: L17.4@122.334,126.5 122.334,125.704 v1(122.688,125.35)
NetIC4_1: IC4.1 IC4.4 R26.1 | length 6.7
  Bottom Layer w0.203: IC4.1@171.7,141.363 172.122,141.363 174.022,143.263 IC4.4@174.3,143.263
  Bottom Layer w0.508: R26.1@169.863,138.808 169.863,139.526 IC4.1@171.7,141.363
